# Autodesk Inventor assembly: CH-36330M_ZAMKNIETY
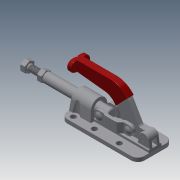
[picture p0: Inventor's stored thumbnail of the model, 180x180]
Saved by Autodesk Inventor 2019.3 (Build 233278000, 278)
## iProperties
Company: Î¢ÈíÖÐ¹ú
Created: 2012-09
Part Number: CH-36330M_ZAMKNIETY
Material: Ogólny
Description: STEP AP203
Document SubType Name: Assembly
Designer: CADENGINEERING4
Sending System: SolidWorks 2010
Preprocessor: SwSTEP 2.0
Title: CH-36330M.STEP
Author: Î¢ÈíÓÃ»§
Revision Number: ÈÎºÎ
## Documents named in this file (11)
- D:\Vault_2016\Projekty\STRONA\Push-pull clamp\CH-36330M\CH-36330M_ZAMKNIETY.iam
- D:\Vault_2016\Projekty\STRONA\Push-pull clamp\CH-36330M\CH-36330M-01 BASE.ipt
- D:\Vault_2016\Projekty\STRONA\Push-pull clamp\CH-36330M\CH-36330M-02 CREST STALK.ipt
- D:\Vault_2016\Projekty\STRONA\Push-pull clamp\CH-36330M\M10 Nut.ipt
- D:\Vault_2016\Projekty\STRONA\Push-pull clamp\CH-36330M\CH-36330M-07.ipt
- D:\Vault_2016\Projekty\STRONA\Push-pull clamp\CH-36330M\CH-36330M-03 HANDLE.ipt
- D:\Vault_2016\Projekty\STRONA\Push-pull clamp\CH-36330M\CH-36330M-04 CONNECTING-PLATE.ipt
- D:\Vault_2016\Projekty\STRONA\Push-pull clamp\CH-36330M\CH-36330M-08.ipt
- D:\Vault_2016\Projekty\STRONA\Push-pull clamp\CH-36330M\CH-36330M-05.ipt
- D:\Vault_2016\Projekty\STRONA\Push-pull clamp\CH-36330M\CH-36330M-06.ipt
- D:\Vault_2016\Projekty\STRONA\Push-pull clamp\CH-36330M\CH-SA-105015 SPINDLE SUPPLIED.ipt
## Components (11 placed, 11 different names)
1. CH-36330M-01 BASE_1
2. CH-36330M-02 CREST STALK_2
3. M10 Nut_3
4. CH-36330M-07_4
5. CH-36330M-03 HANDLE_5
6. CH-36330M-04 CONNECTING-PLATE_6
7. CH-36330M-04 CONNECTING-PLATE_7
8. CH-36330M-08_8
9. CH-36330M-05_9
10. CH-36330M-06_10
11. CH-SA-105015 SPINDLE SUPPLIED_11
